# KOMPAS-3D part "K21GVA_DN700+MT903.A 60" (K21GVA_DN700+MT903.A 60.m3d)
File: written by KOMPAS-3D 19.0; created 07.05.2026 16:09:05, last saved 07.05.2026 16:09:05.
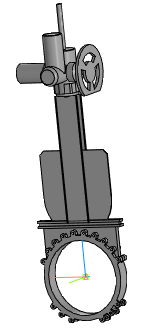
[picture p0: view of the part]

Document properties: Автор: Энергия; Полное имя файла: ..\K21GVA_DN50-DN1000+MT903.A\K21GVA_DN600+MT903.A 60.a3d

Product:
- Part/product: K21GVA_DN700+MT903.A 60
    Масса: 601.638

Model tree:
1. Операция без истории:1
